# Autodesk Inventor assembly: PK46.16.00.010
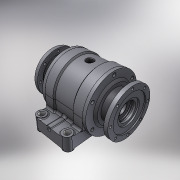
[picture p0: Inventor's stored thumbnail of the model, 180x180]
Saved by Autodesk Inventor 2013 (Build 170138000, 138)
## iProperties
Shininess: 64.0
Length Units: 11269
Angle Units: 11279
Time Units: 11290
Mass Units: 11283
Length Display Precision: 3
Angle Display Precision: 2
Compacted: True
Created: 2004-12
Part Number: PK46.16.00.010
Document SubType Name: Assembly
Designer: Salex
Manufacturer: Standard
Standards Organization: Custom
Mass: 20401.2 g
Surface Area: 8884.82 cm^2
Volume: 5540.42 cm^3
Density: 3.68224 g/cm^3
Density: 0.0
Volumn: 0.0
Area: 0.0
PropertySet Name: Model Information
Control State: 0
Master: False
Checked Out: False
Checked Out Date: 2008-10-09
Last Check In Date: 2008-10-09
Author: Salex
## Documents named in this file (7)
- C:\Product Design Suite 2013 Test Drive\Dynamic Simulation\Workspace\Assy, Chassis, Front\PK46.16.10.000.iam
- C:\Product Design Suite 2013 Test Drive\Dynamic Simulation\Workspace\Assy, Chassis, Front\TO-40.16.00.011.ipt
- C:\Product Design Suite 2013 Test Drive\Dynamic Simulation\Workspace\Assy, Chassis, Front\TO-40.10.05.011.ipt
- C:\Product Design Suite 2013 Test Drive\Dynamic Simulation\Workspace\Assy, Chassis, Front\PK46.16.00.010.ipt
- C:\Product Design Suite 2013 Test Drive\Dynamic Simulation\Workspace\Assy, Chassis, Front\TO-40.20.00.011.ipt
- C:\Product Design Suite 2013 Test Drive\Dynamic Simulation\Workspace\Assy, Chassis, Front\TO-40.25.00.011.ipt
- C:\Product Design Suite 2013 Test Drive\Dynamic Simulation\Workspace\Assy, Chassis, Front\M10-6gx25.58.019.ipt
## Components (20 placed, 6 different names)
1. TO-40.16.00.011:1 — Вставка:1, Совмещение:1, Вставка:2, Вставка:3, Совмещение:2, Угол:2, Вставка:4, Insert:6, Insert:7
2. TO-40.10.05.011:1 — Вставка:2, Угол:1
3. TO-40.10.05.011:2 — Вставка:1, Совмещение:1, Угол:1
4. PK46.16.00.010:1 — Вставка:3, Flush:1
5. PK46.16.00.010:2 — Вставка:4
6. TO-40.20.00.011:1 — Flush:2, Insert:3, Insert:5
7. TO-40.25.00.011:1 — Insert:3
8. TO-40.25.00.011:2 — Insert:5
9. M10-6gx25.58.019:2 — Insert:7
10. M10-6gx25.58.019:1 — Insert:6
11. M10-6gx25.58.019:3
12. M10-6gx25.58.019:4
13. M10-6gx25.58.019:5
14. M10-6gx25.58.019:6
15. M10-6gx25.58.019:7
16. M10-6gx25.58.019:8
17. M10-6gx25.58.019:9
18. M10-6gx25.58.019:10
19. M10-6gx25.58.019:11
20. M10-6gx25.58.019:12
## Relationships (14: Insert 8, Mate 2, Angle 2, Flush 2)
- Вставка:1 [Insert]: TO-40.16.00.011:1 ↔ TO-40.10.05.011:2
- Совмещение:1 [Mate]: TO-40.16.00.011:1 ↔ TO-40.10.05.011:2
- Вставка:2 [Insert]: TO-40.16.00.011:1 ↔ TO-40.10.05.011:1
- Вставка:3 [Insert]: TO-40.16.00.011:1 ↔ PK46.16.00.010:1
- Угол:1 [Angle]: TO-40.10.05.011:1 ↔ TO-40.10.05.011:2
- Совмещение:2 [Mate]: TO-40.16.00.011:1
- Угол:2 [Angle]: TO-40.16.00.011:1
- Вставка:4 [Insert]: TO-40.16.00.011:1 ↔ PK46.16.00.010:2
- Flush:1: PK46.16.00.010:1
- Flush:2: TO-40.20.00.011:1
- Insert:3: TO-40.20.00.011:1 ↔ TO-40.25.00.011:1
- Insert:5: TO-40.20.00.011:1 ↔ TO-40.25.00.011:2
- Insert:6: TO-40.16.00.011:1 ↔ M10-6gx25.58.019:1
- Insert:7: TO-40.16.00.011:1 ↔ M10-6gx25.58.019:2
